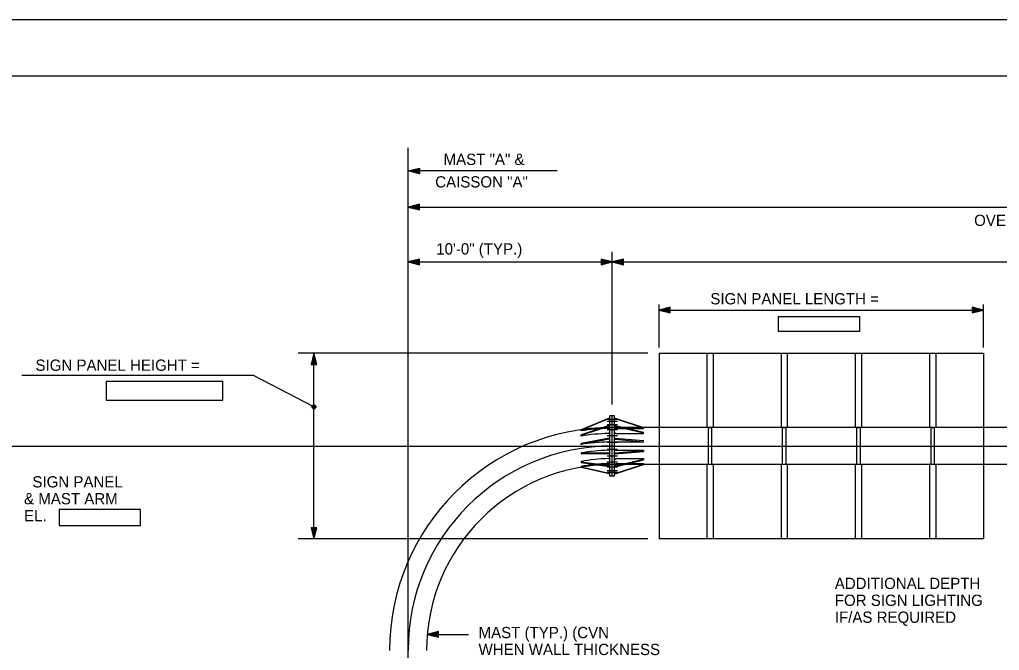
# Model space of a CAD drawing. Extents: x 640117 to 642655, y 297247 to 298435.
# Drawn here: x 641182.8 to 641443.9, y 298267.5 to 298435.5 of the extents above; entities that cross this region are included whole.
import ezdxf

# ---------------------------------------------------------------- set-up
doc = ezdxf.new("R2010")
doc.units = 0
for name, color, linetype in [('2', 7, 'Continuous'), ('48', 7, 'Continuous'), ('49', 7, 'Continuous'), ('50', 7, 'Continuous'), ('52', 7, 'Continuous'), ('53', 7, 'Continuous'), ('55', 7, 'Continuous'), ('PLT-BNDY', 7, 'Continuous')]:
    doc.layers.add(name, color=color, linetype=linetype)

msp = doc.modelspace()

# ---------------------------------------------------------------- linework, layer by layer
at = {"layer": '2'}
msp.add_line((640998.46, 298420.46), (641784.46, 298420.46), dxfattribs=at)
for points in [[(641385.09, 298356.38), (641406.64, 298356.38), (641406.64, 298352.38), (641385.09, 298352.38)], [(641205.85, 298334.14), (641237.01, 298334.14), (641237.01, 298339.12), (641205.85, 298339.12)], [(641193.32, 298300.75), (641215.07, 298300.75), (641215.07, 298305), (641193.32, 298305)]]:
    msp.add_lwpolyline(points, close=True, dxfattribs=at)
at = {"layer": '48'}
for p, q in [((641342.15, 298328.95), (641339.38, 298328.95)), ((641342.15, 298328.47), (641339.38, 298328.47)), ((641342.15, 298327.54), (641339.38, 298327.54)), ((641342.15, 298326.23), (641339.38, 298326.23)), ((641342.15, 298324.62), (641339.38, 298324.62)), ((641342.15, 298322.83), (641339.38, 298322.83)), ((641342.15, 298320.97), (641339.38, 298320.97)), ((641342.15, 298319.18), (641339.38, 298319.18)), ((641342.15, 298317.57), (641339.38, 298317.57)), ((641342.15, 298316.25), (641339.38, 298316.25)), ((641342.15, 298315.33), (641339.38, 298315.33)), ((641342.15, 298314.85), (641339.38, 298314.85))]:
    msp.add_line(p, q, dxfattribs=at)
at = {"layer": '49'}
for p, q in [((641353.24, 298346.63), (641353.24, 298326.84)), ((641353.24, 298346.63), (641439.71, 298346.63)), ((641365.97, 298346.63), (641365.97, 298326.84)), ((641367.62, 298346.63), (641367.62, 298326.84)), ((641385.76, 298346.63), (641385.76, 298326.84)), ((641387.41, 298346.63), (641387.41, 298326.84)), ((641405.55, 298346.63), (641405.55, 298326.84)), ((641407.19, 298346.63), (641407.19, 298326.84)), ((641425.33, 298346.63), (641425.33, 298326.84)), ((641426.98, 298346.63), (641426.98, 298326.84)), ((641439.71, 298346.63), (641439.71, 298326.84)), ((641353.24, 298326.84), (641353.24, 298316.95)), ((641439.71, 298326.84), (641439.71, 298316.95)), ((641353.24, 298316.95), (641353.24, 298297.16)), ((641365.97, 298316.95), (641365.97, 298297.16)), ((641367.62, 298316.95), (641367.62, 298297.16)), ((641385.76, 298316.95), (641385.76, 298297.16)), ((641387.41, 298316.95), (641387.41, 298297.16)), ((641405.55, 298316.95), (641405.55, 298297.16)), ((641407.19, 298316.95), (641407.19, 298297.16)), ((641425.33, 298316.95), (641425.33, 298297.16)), ((641426.98, 298316.95), (641426.98, 298297.16)), ((641439.71, 298316.95), (641439.71, 298297.16)), ((641439.71, 298297.16), (641353.24, 298297.16))]:
    msp.add_line(p, q, dxfattribs=at)
for points in [[(641366.4, 298326.84), (641367.22, 298326.84), (641367.22, 298316.95), (641366.4, 298316.95)], [(641386.18, 298326.84), (641387.01, 298326.84), (641387.01, 298316.95), (641386.18, 298316.95)], [(641405.97, 298326.84), (641406.8, 298326.84), (641406.8, 298316.95), (641405.97, 298316.95)], [(641425.76, 298326.84), (641426.58, 298326.84), (641426.58, 298316.95), (641425.76, 298316.95)]]:
    msp.add_lwpolyline(points, close=True, dxfattribs=at)
at = {"layer": '50'}
for p, q in [((641286.35, 298152.28), (641286.35, 298401.29)), ((641032.47, 298321.9), (641730.35, 298321.9))]:
    msp.add_line(p, q, dxfattribs=at)
msp.add_arc((641340.77, 298267.48), 54.42, 90, 180, dxfattribs=at)
at = {"layer": '52'}
for p, q in [((641326.09, 298395.18), (641286.35, 298395.18)), ((641289.35, 298386.27), (641286.35, 298385.52)), ((641286.35, 298385.52), (641289.35, 298384.77)), ((641286.35, 298385.52), (641662.33, 298385.52)), ((641289.18, 298386.04), (641287.09, 298385.52)), ((641287.09, 298385.52), (641289.18, 298385)), ((641289, 298385.81), (641287.82, 298385.52)), ((641287.82, 298385.52), (641289, 298385.22)), ((641288.93, 298385.61), (641288.55, 298385.52)), ((641288.55, 298385.52), (641288.91, 298385.43)), ((641289, 298385.22), (641289, 298385.81)), ((641289.18, 298385), (641289.18, 298386.04)), ((641289.35, 298384.77), (641289.35, 298386.27)), ((641289.35, 298371.66), (641286.35, 298370.91)), ((641289.18, 298371.44), (641287.09, 298370.91)), ((641289.18, 298370.39), (641289.18, 298371.44)), ((641289.35, 298370.16), (641289.35, 298371.66)), ((641340.77, 298370.91), (641337.77, 298371.66)), ((641337.77, 298371.66), (641337.77, 298370.16)), ((641340.04, 298370.91), (641337.95, 298371.44)), ((641337.95, 298371.44), (641337.95, 298370.39)), ((641340.77, 298332.93), (641340.77, 298373.65)), ((641343.77, 298371.66), (641340.77, 298370.91)), ((641343.59, 298371.44), (641341.5, 298370.91)), ((641343.59, 298370.39), (641343.59, 298371.44)), ((641343.77, 298370.16), (641343.77, 298371.66)), ((641286.35, 298370.91), (641289.35, 298370.16)), ((641287.09, 298370.91), (641289.18, 298370.39)), ((641289, 298371.21), (641287.82, 298370.91)), ((641287.82, 298370.91), (641289, 298370.62)), ((641288.93, 298371.01), (641288.55, 298370.91)), ((641288.55, 298370.91), (641288.91, 298370.82)), ((641289, 298370.62), (641289, 298371.21)), ((641337.77, 298370.16), (641340.77, 298370.91)), ((641337.95, 298370.39), (641340.04, 298370.91)), ((641339.3, 298370.91), (641338.12, 298371.21)), ((641338.12, 298371.21), (641338.12, 298370.62)), ((641338.12, 298370.62), (641339.3, 298370.91)), ((641338.2, 298370.82), (641338.57, 298370.91)), ((641338.57, 298370.91), (641338.21, 298371)), ((641340.77, 298370.91), (641343.77, 298370.16)), ((641341.5, 298370.91), (641343.59, 298370.39)), ((641343.42, 298371.21), (641342.24, 298370.91)), ((641342.24, 298370.91), (641343.42, 298370.62)), ((641343.34, 298371.01), (641342.97, 298370.91)), ((641342.97, 298370.91), (641343.33, 298370.82)), ((641343.42, 298370.62), (641343.42, 298371.21)), ((641353.24, 298348.13), (641353.24, 298359.59)), ((641356.24, 298358.84), (641353.24, 298358.09)), ((641356.06, 298358.61), (641353.97, 298358.09)), ((641355.88, 298358.39), (641354.71, 298358.09)), ((641355.81, 298358.18), (641355.44, 298358.09)), ((641355.88, 298357.8), (641355.88, 298358.39)), ((641356.06, 298357.57), (641356.06, 298358.61)), ((641356.24, 298357.34), (641356.24, 298358.84)), ((641439.71, 298358.09), (641436.71, 298358.84)), ((641436.71, 298358.84), (641436.71, 298357.34)), ((641438.98, 298358.09), (641436.89, 298358.61)), ((641436.89, 298358.61), (641436.89, 298357.57)), ((641438.25, 298358.09), (641437.07, 298358.39)), ((641437.07, 298358.39), (641437.07, 298357.8)), ((641437.51, 298358.09), (641437.16, 298358.18)), ((641439.71, 298348.13), (641439.71, 298359.59)), ((641353.24, 298358.09), (641439.71, 298358.09)), ((641353.24, 298358.09), (641356.24, 298357.34)), ((641353.97, 298358.09), (641356.06, 298357.57)), ((641354.71, 298358.09), (641355.88, 298357.8)), ((641355.44, 298358.09), (641355.79, 298358)), ((641436.71, 298357.34), (641439.71, 298358.09)), ((641436.89, 298357.57), (641438.98, 298358.09)), ((641437.07, 298357.8), (641438.25, 298358.09)), ((641437.14, 298358), (641437.51, 298358.09)), ((641350.27, 298346.63), (641257.06, 298346.63)), ((641261.25, 298346.63), (641260.5, 298343.63)), ((641261.25, 298345.9), (641260.73, 298343.81)), ((641261.25, 298345.17), (641260.96, 298343.99)), ((641261.25, 298297.16), (641261.25, 298346.63)), ((641262, 298343.63), (641261.25, 298346.63)), ((641261.77, 298343.81), (641261.25, 298345.9)), ((641261.55, 298343.99), (641261.25, 298345.17)), ((641260.5, 298343.63), (641262, 298343.63)), ((641260.73, 298343.81), (641261.77, 298343.81)), ((641260.96, 298343.99), (641261.55, 298343.99)), ((641261.25, 298344.43), (641261.16, 298344.08)), ((641261.34, 298344.06), (641261.25, 298344.43)), ((641260.5, 298300.16), (641261.25, 298297.16)), ((641262, 298300.16), (641260.5, 298300.16)), ((641260.73, 298299.98), (641261.25, 298297.89)), ((641261.77, 298299.98), (641260.73, 298299.98)), ((641260.96, 298299.81), (641261.25, 298298.63)), ((641261.55, 298299.81), (641260.96, 298299.81)), ((641261.16, 298299.74), (641261.25, 298299.36)), ((641261.25, 298297.16), (641262, 298300.16)), ((641261.25, 298297.89), (641261.77, 298299.98)), ((641261.25, 298298.63), (641261.55, 298299.81)), ((641261.25, 298299.36), (641261.34, 298299.72)), ((641350.27, 298297.16), (641257.06, 298297.16)), ((641294.48, 298272.48), (641291.48, 298271.73)), ((641294.31, 298272.25), (641292.22, 298271.73)), ((641294.13, 298272.02), (641292.95, 298271.73)), ((641294.13, 298271.43), (641294.13, 298272.02)), ((641294.31, 298271.21), (641294.31, 298272.25)), ((641294.48, 298270.98), (641294.48, 298272.48)), ((641291.48, 298271.73), (641294.48, 298270.98)), ((641292.22, 298271.73), (641294.31, 298271.21)), ((641292.95, 298271.73), (641294.13, 298271.43)), ((641294.06, 298271.82), (641293.68, 298271.73)), ((641293.68, 298271.73), (641294.04, 298271.64))]:
    msp.add_line(p, q, dxfattribs=at)
for points in [[(641286.35, 298370.91), (641676.82, 298370.91)], [(641261.25, 298332.33), (641245.12, 298340.7), (641183.37, 298340.7)], [(641291.48, 298271.73), (641302.48, 298271.73)]]:
    msp.add_lwpolyline(points, dxfattribs=at)
for radius in [0.536, 0.268]:
    msp.add_circle((641261.25, 298332.33), radius, dxfattribs=at)
at = {"layer": '53'}
for p, q in [((641286.35, 298395.18), (641289.35, 298395.93)), ((641289.35, 298394.43), (641286.35, 298395.18)), ((641287.09, 298395.18), (641289.18, 298395.7)), ((641289.18, 298394.66), (641287.09, 298395.18)), ((641287.82, 298395.18), (641289, 298395.47)), ((641289, 298394.88), (641287.82, 298395.18)), ((641288.55, 298395.18), (641288.91, 298395.27)), ((641288.93, 298395.09), (641288.55, 298395.18)), ((641289, 298395.47), (641289, 298394.88)), ((641289.18, 298395.7), (641289.18, 298394.66)), ((641289.35, 298395.93), (641289.35, 298394.43))]:
    msp.add_line(p, q, dxfattribs=at)
at = {"layer": '55'}
for p, q in [((641341.38, 298329.92), (641340.16, 298329.92)), ((641340.16, 298313.87), (641340.16, 298329.92)), ((641340.77, 298313.87), (641340.77, 298329.92)), ((641341.38, 298313.87), (641341.38, 298329.92)), ((641339.96, 298329.3), (641332.44, 298326.19)), ((641339.96, 298329.22), (641332.44, 298326.11)), ((641339.96, 298327.39), (641332.44, 298324.92)), ((641339.96, 298327.18), (641332.44, 298324.71)), ((641340.16, 298326.96), (641339.75, 298326.57)), ((641340.16, 298329.3), (641339.96, 298329.3)), ((641340.16, 298329.22), (641339.96, 298329.22)), ((641340.16, 298327.39), (641339.96, 298327.39)), ((641340.16, 298327.18), (641339.96, 298327.18)), ((641474.34, 298326.84), (641340.77, 298326.84)), ((641341.38, 298329.3), (641341.58, 298329.3)), ((641341.38, 298329.22), (641341.58, 298329.22)), ((641341.38, 298327.39), (641341.58, 298327.39)), ((641341.38, 298327.18), (641341.58, 298327.18)), ((641341.38, 298326.96), (641341.79, 298326.57)), ((641341.58, 298329.3), (641349.1, 298326.84)), ((641341.58, 298329.22), (641349.1, 298326.76)), ((641341.58, 298327.39), (641349.1, 298325.59)), ((641341.58, 298327.18), (641349.1, 298325.38)), ((641349.1, 298326.57), (641349.1, 298326.84)), ((641336.51, 298326.57), (641332.44, 298325.91)), ((641332.44, 298325.91), (641332.44, 298326.19)), ((641332.44, 298324.57), (641332.44, 298324.92)), ((641339.75, 298326.57), (641336.51, 298326.57)), ((641340.16, 298325.52), (641339.75, 298325.24)), ((641349.1, 298326.77), (641341.38, 298326.77)), ((641341.38, 298325.52), (641341.79, 298325.24)), ((641341.79, 298326.57), (641345.03, 298326.57)), ((641341.79, 298325.24), (641349.1, 298325.24)), ((641345.03, 298326.57), (641349.1, 298326.57)), ((641349.1, 298325.24), (641349.1, 298325.59)), ((641339.96, 298324.02), (641332.44, 298322.61)), ((641339.96, 298323.72), (641332.44, 298322.31)), ((641332.44, 298322.26), (641332.44, 298322.61)), ((641340.16, 298323.12), (641339.75, 298323.01)), ((641340.16, 298324.02), (641339.96, 298324.02)), ((641340.16, 298323.72), (641339.96, 298323.72)), ((641341.38, 298324.02), (641341.58, 298324.02)), ((641341.38, 298323.72), (641341.58, 298323.72)), ((641341.38, 298323.12), (641341.79, 298323.01)), ((641341.58, 298324.02), (641349.1, 298323.36)), ((641341.58, 298323.72), (641349.1, 298323.06)), ((641341.79, 298323.01), (641349.1, 298323.01)), ((641349.1, 298323.01), (641349.1, 298323.36)), ((641339.96, 298320.07), (641332.44, 298320)), ((641332.44, 298320.05), (641332.44, 298319.7)), ((641339.96, 298319.78), (641332.44, 298319.7)), ((641340.16, 298320.68), (641339.75, 298320.78)), ((641340.16, 298320.07), (641339.96, 298320.07)), ((641340.16, 298319.78), (641339.96, 298319.78)), ((641341.38, 298320.68), (641341.79, 298320.78)), ((641341.38, 298320.07), (641341.58, 298320.07)), ((641341.38, 298319.78), (641341.58, 298319.78)), ((641341.58, 298320.07), (641349.1, 298320.73)), ((641341.58, 298319.78), (641349.1, 298320.44)), ((641341.79, 298320.78), (641349.1, 298320.78)), ((641349.1, 298320.78), (641349.1, 298320.44)), ((641332.44, 298317.79), (641332.44, 298317.43)), ((641339.96, 298316.62), (641332.44, 298317.64)), ((641339.96, 298316.4), (641332.44, 298317.43)), ((641332.44, 298316.43), (641332.44, 298316.16)), ((641340.16, 298318.27), (641339.75, 298318.56)), ((641340.16, 298316.84), (641339.75, 298317.23)), ((641340.16, 298316.62), (641339.96, 298316.62)), ((641340.16, 298316.4), (641339.96, 298316.4)), ((641456.82, 298316.95), (641340.77, 298316.95)), ((641341.38, 298318.27), (641341.79, 298318.56)), ((641341.38, 298316.84), (641341.79, 298317.23)), ((641349.1, 298317.02), (641341.38, 298317.02)), ((641341.38, 298316.62), (641341.58, 298316.62)), ((641341.38, 298316.4), (641341.58, 298316.4)), ((641341.58, 298316.62), (641349.1, 298318.41)), ((641341.58, 298316.4), (641349.1, 298318.2)), ((641341.58, 298314.58), (641349.1, 298317.03)), ((641341.58, 298314.5), (641349.1, 298316.95)), ((641341.79, 298318.56), (641349.1, 298318.56)), ((641341.79, 298317.23), (641345.03, 298317.23)), ((641345.03, 298317.23), (641349.1, 298317.23)), ((641349.1, 298318.56), (641349.1, 298318.2)), ((641349.1, 298317.23), (641349.1, 298316.95)), ((641339.96, 298314.58), (641332.44, 298316.24)), ((641339.96, 298314.5), (641332.44, 298316.16)), ((641340.16, 298314.58), (641339.96, 298314.58)), ((641340.16, 298314.5), (641339.96, 298314.5)), ((641341.38, 298313.87), (641340.16, 298313.87)), ((641341.38, 298314.58), (641341.58, 298314.58)), ((641341.38, 298314.5), (641341.58, 298314.5))]:
    msp.add_line(p, q, dxfattribs=at)
for centre, radius, start, end in [((641340.77, 298267.48), 59.36, 90, 180), ((641340.77, 298273.13), 53.64, 90, 98.9344), ((641340.77, 298273.13), 53.44, 91.0894, 98.969), ((641340.77, 298273.13), 52.11, 91.1172, 99.2), ((641340.77, 298273.13), 49.88, 91.167, 99.6143), ((641340.77, 298273.13), 47.65, 91.2217, 100.0688), ((641340.77, 298267.48), 49.47, 90, 180), ((641340.77, 298273.13), 45.43, 91.2815, 100.5676), ((641340.77, 298273.13), 43.89, 90, 100.942), ((641340.77, 298273.13), 44.1, 96.3442, 100.8903), ((641340.77, 298273.13), 44.1, 91.3202, 96.3442)]:
    msp.add_arc(centre, radius, start, end, dxfattribs=at)
at = {"layer": 'PLT-BNDY'}
msp.add_lwpolyline([(640958.46, 298435.46), (641799.46, 298435.46), (641799.46, 297841.46), (640958.46, 297841.46)], close=True, dxfattribs=at)

# ---------------------------------------------------------------- texts
at = {"layer": '2'}
for s, p in [('10\'-0" (TYP.)', (641293.86, 298372.9)), ('SIGN PANEL HEIGHT =', (641187.05, 298341.93)), ('  SIGN PANEL', (641184, 298310.87)), ('& MAST ARM', (641184, 298306.37)), ('EL.', (641184, 298301.87)), ('ADDITIONAL DEPTH', (641400.08, 298283.82)), ('FOR SIGN LIGHTING', (641400.08, 298279.32)), ('IF/AS REQUIRED', (641400.08, 298274.82)), ('MAST (TYP.) (CVN', (641305.14, 298270.73)), ('WHEN WALL THICKNESS', (641305.14, 298266.23))]:
    msp.add_text(s, height=3, dxfattribs=at).set_placement(p)
at = {"layer": '52'}
msp.add_text('OVERALL LENGTH =', height=3, dxfattribs=at).set_placement((641437.21, 298380.51))
at = {"layer": '53'}
for s, p in [('  MAST "A" &', (641293.58, 298396.75)), ('CAISSON "A"', (641293.58, 298390.75)), ('SIGN PANEL LENGTH =', (641366.91, 298359.62))]:
    msp.add_text(s, height=3, dxfattribs=at).set_placement(p)

doc.saveas('drawing.dxf')
